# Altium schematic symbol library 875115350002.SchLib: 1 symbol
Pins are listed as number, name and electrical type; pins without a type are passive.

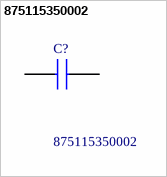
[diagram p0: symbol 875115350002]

## 875115350002
designator C?
Wurth Elektronik 220uF 16 V dc Aluminium Polymer Capacitor, WCAP-PSHP Series 2000h 7.7 (Dia.) x 7.55mm; Geometry.Height: 7.7mm
footprint CAPAE830X770N
pins: 1 +, 2 -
